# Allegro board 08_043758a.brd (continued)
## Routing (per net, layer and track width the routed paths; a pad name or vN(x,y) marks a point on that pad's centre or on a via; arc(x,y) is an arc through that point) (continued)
ADM1177_SCL: length 49.8
  TOP w0.127: U11.7 64.81,13.61 R81.2 65.9,12.52 67.54,12.52 69.31,10.74 v1(74.14,10.74) ; U10.6 v1(90.78,38.16)
  L5_SIG w0.127: v1(90.78,38.16) 89.77,37.15 89.77,28.31 83.13,21.66 79.35,21.66 78.08,20.4 78.08,14.69 v1(74.14,10.74)
ADM1177_SDA: length 50.7
  TOP w0.127: U11.6 64.37,12.96 64.62,12.71 64.62,12.28 R80.2 65.9,12.27 67.16,12.27 69.19,10.23 73.76,10.23 v1(74.14,9.85) ; v1(90.78,37.28) 90.4,37.66 U10.7
  L5_SIG w0.127: v1(74.14,9.85) 78.59,14.3 78.59,20.14 79.6,21.16 83.16,21.16 90.27,28.27 90.27,36.78 v1(90.78,37.28)
ADP2114_VIN: length 19.9
  TOP w0.203: U6.31 95.2,47.46 95.48,47.19
  TOP w0.305: U6.4 97.13,50.24 v1(97.25,50.37) ; C141.1 97.11,52.24 U6.8 ; C141.1 98.08,53.21 R56.2 98.08,54.49 v1(97.89,54.68) ; C141.1 97.14,53.79 95.51,53.79 95.2,53.49 U6.10 ; v1(97.25,46.94) 95.73,46.94 95.48,47.19
  L5_SIG w0.305: v1(97.25,46.94) 98,47.68 98,49.24 97.25,49.98 v1(97.25,50.37) 97.59,50.37 97.89,50.67 v1(97.89,54.68)
COMP_1P8V: length 2.8
  TOP w0.305: v1(97.25,49.1) 97.11,49.24 U6.2
  BOTTOM w0.508: v1(97.25,49.1) 97.38,48.97 R60.1 C142.2
COMP_1P35V: length 2.7
  TOP w0.305: C143.2 98.01,51.74 U6.7
  TOP w0.406: C143.2 98.03,51.76 C144.1
CTRL_IN0: length 53
  TOP w0.102: U4.F13 v2(56.33,28.95) ; U5.C5 v2(33.14,33.68)
  L6_SIG w0.114: v2(33.14,33.68) 33.15,33.68 33.55,34.08 33.55,34.68 33.35,34.88 31.22,34.88 30.34,34.01 30.34,32.68 30.15,32.48 28.15,32.48 27.15,31.48 27.15,25.23 30.2,22.17 53.36,22.17 56.72,25.53 56.72,26.91 56.33,27.31 v2(56.33,28.95)
CTRL_IN1: length 48
  TOP w0.102: U5.C6 v2(33.14,32.88) ; v2(56.33,26.55) 56.33,28.14 55.93,28.54 U4.F14
  L6_SIG w0.114: v2(33.14,32.88) 33.14,32.89 32.75,33.28 32.75,33.88 32.55,34.08 31.75,34.08 30.82,33.15 30.82,32.75 30.11,32.05 29.71,32.05 29.32,31.66 28.12,31.66 27.94,31.48 27.94,25.06 30.33,22.68 53.27,22.68 56.33,25.74 v2(56.33,26.55)
CTRL_IN2: length 38.6
  TOP w0.102: U5.D6 v2(32.34,32.88) ; v2(55.53,27.35) U4.G15
  L6_SIG w0.114: v2(55.53,27.35) 54.96,26.78 54.96,26.37 54.66,26.07 54.06,26.07 52.19,24.2 30.96,24.2 29.55,25.62 29.55,26.18 29.95,26.58 29.95,27.58 29.55,27.98 29.55,30.68 29.75,30.88 30.15,30.88 30.35,31.08 30.35,31.48 31.22,32.35 31.61,32.35 32.14,32.88 v2(32.34,32.88)
CTRL_IN3: length 41.6
  TOP w0.102: U4.F15 55.93,26.95 v2(55.53,26.55) ; U5.D5 v2(32.34,33.68)
  L6_SIG w0.114: v2(32.34,33.68) U5.D5 31.34,33.28 31.12,33.05 31.12,32.65 30.17,31.7 29.76,31.7 29.55,31.48 29.55,31.08 29.35,30.88 28.95,30.88 28.42,30.35 28.42,26.11 30.71,23.82 52.61,23.82 53.98,25.18 54.97,25.18 55.53,25.75 v2(55.53,26.55)
DDR3_A0: length 30.1
  TOP w0.165: U2.N3 51.22,54.27 v2(51.22,54.27) ; U4.P1 49.03,39.45 48.43,39.45 47.03,40.85 v2(43.92,40.85)
  L6_SIG w0.165: v2(43.92,40.85) 43.32,41.45 43.32,42.04 43.52,42.23 43.91,42.23 44.11,42.43 44.11,42.71 43.91,42.91 43.52,42.91 43.32,43.1 43.32,43.38 43.52,43.58 43.91,43.58 44.11,43.78 44.11,44.06 43.91,44.25 43.52,44.25 43.32,44.45 43.32,47.48 46.51,50.67 49.02,50.67 49.41,51.07 49.41,51.87 51.22,53.68 v2(51.22,54.27)
  BOTTOM w0.165: v2(51.22,54.27) 51.62,54.67 51.62,56.16 R16.1
DDR3_A1: length 33.2
  TOP w0.165: v2(43.92,41.65) 46.93,41.65 48.63,39.95 49.33,39.95 U4.N1 ; U2.P7 49.83,51.66 v2(48.03,51.66)
  L6_SIG w0.165: v2(48.03,51.66) 46,51.66 45.38,51.03 45.1,51.03 44.83,51.31 44.55,51.31 44.35,51.11 44.35,50.83 44.62,50.56 44.62,50.28 44.43,50.08 44.15,50.08 43.88,50.35 43.6,50.35 43.4,50.16 43.4,49.88 43.67,49.61 43.67,49.33 43.47,49.13 43.07,49.13 42.72,48.78 42.72,48.38 42.51,48.17 42.51,40.56 43.61,39.46 44.21,39.46 44.41,39.66 44.41,41.16 v2(43.92,41.65)
  BOTTOM w0.165: v2(48.03,51.66) 47.45,51.66 R22.1
DDR3_A2: length 35.7
  TOP w0.165: U2.P3 v2(50.42,54.27) ; U4.M1 51.13,39.75 v2(49.93,40.95)
  L5_SIG w0.165: v2(49.93,40.95) 49.53,40.95 49.23,40.65 49.23,40.35 49.93,39.65 49.93,39.35 49.53,38.95 49.53,37.95 49.13,37.55 48.93,37.55 48.73,37.75 48.73,38.75 48.53,38.95 48.23,38.95 48.03,38.75 48.03,37.65 47.87,37.49 47.59,37.49 45.83,39.25 45.83,51.2 48.5,53.87 50.02,53.87 v2(50.42,54.27)
  BOTTOM w0.165: v2(50.42,54.27) 50.02,53.87 49.3,53.87 48.61,54.56 47.45,54.56 R17.1
DDR3_A3: length 31.5
  TOP w0.165: U4.M4 v2(50.73,36.95) ; U2.N2 v2(51.22,55.07)
  L5_SIG w0.165: v2(50.73,36.95) 51.02,36.95 51.13,37.06 51.13,37.97 51.48,38.33 51.48,38.63 51.28,38.83 50.9,38.83 50.73,39 50.73,42.75 50.53,42.95 49.93,42.95 49.53,43.35 49.53,44.55 49.71,44.73 50.13,44.73 50.33,44.93 50.33,45.21 50.13,45.4 49.73,45.4 49.53,45.6 49.53,45.88 49.73,46.08 50.13,46.08 50.33,46.27 50.33,46.55 50.13,46.75 49.73,46.75 49.53,46.95 49.53,47.23 49.73,47.42 50.13,47.42 50.33,47.62 50.33,48.06 50.12,48.27 49.92,48.27 49.73,48.46 49.73,49.56 50.04,49.87 50.64,49.87 50.82,50.04 50.82,51.73 51,51.92 51.51,51.92 51.69,52.09 51.69,52.58 51.85,52.74 52.59,52.74 52.75,52.9 52.75,53.12 52.59,53.28 51.85,53.28 51.69,53.44 51.69,53.74 51.85,53.9 52.6,53.9 52.76,54.06 52.76,54.28 52.6,54.44 51.65,54.44 51.46,54.63 51.46,54.83 v2(51.22,55.07)
  BOTTOM w0.165: v2(51.22,55.07) 50.94,55.07 50.82,55.2 50.82,56.16 R23.1
DDR3_A4: length 26.7
  TOP w0.165: v2(50.42,50.27) U2.P8 ; v2(47.33,38.65) 48.23,37.75 49.13,37.75 U4.P3
  L6_SIG w0.165: v2(50.42,50.27) 50.83,49.86 50.83,48.28 50.62,48.07 49.82,48.07 46.41,44.66 46.41,41.76 46.71,41.46 48.91,41.46 49.13,41.25 49.13,40.75 48.84,40.46 48.04,40.46 47.81,40.23 47.81,39.66 47.61,39.46 46.71,39.46 46.51,39.26 46.51,38.46 46.72,38.25 46.93,38.25 v2(47.33,38.65)
  BOTTOM w0.165: R18.1 47.64,50.67 50.02,50.67 v2(50.42,50.27)
DDR3_A5: length 24
  TOP w0.165: U2.P2 v2(50.42,55.07) ; v2(49.11,36.96) U4.P4
  L5_SIG w0.165: v2(49.11,36.96) 49.5,37.35 50.13,37.35 50.33,37.55 50.33,38.05 50.33,38.05 50.45,38.17 50.45,38.73 50.33,38.85 50.33,42.35 50.13,42.55 49.73,42.55 49.13,43.15 49.13,48.16 49.33,48.36 49.33,49.78 50.43,50.88 50.43,51.98 51.23,52.78 51.23,53.56 50.82,53.97 50.82,54.67 v2(50.42,55.07)
  BOTTOM w0.165: v2(50.42,55.07) 50.14,55.07 50.02,55.2 50.02,56.16 R24.1
DDR3_A6: length 26.8
  TOP w0.165: v2(48.01,48.67) 48.81,49.47 49.62,49.47 U2.R8 ; v2(46.72,36.55) 47.13,36.15 49.13,36.15 U4.P5
  L6_SIG w0.165: v2(48.01,48.67) 47.62,49.07 47.29,49.07 47.09,48.87 47.09,48.49 47.33,48.26 47.33,47.96 47.13,47.76 46.63,47.76 46.42,47.96 46.42,48.74 46.29,48.87 46.01,48.87 45.61,48.47 45.61,48.11 45.84,47.88 45.84,47.6 45.65,47.4 45.37,47.4 45.1,47.67 44.82,47.67 44.21,47.07 44.21,45.26 45.21,44.26 45.21,39.16 44.91,38.86 44.91,38.36 v2(46.72,36.55)
  BOTTOM w0.165: R19.1 48.63,48.17 48.52,48.17 v2(48.01,48.67)
DDR3_A7: length 30.3
  TOP w0.165: U4.M5 v2(50.73,36.15) ; U2.R2 v2(49.62,55.07)
  L5_SIG w0.165: v2(49.62,55.07) 49.31,55.37 48.82,55.37 45.02,51.58 45.02,37.95 45.67,37.3 46.57,37.3 47.73,36.15 48.63,36.15 49.03,35.75 50.33,35.75 v2(50.73,36.15)
  BOTTOM w0.165: R25.1 48.12,55.87 48.63,55.36 49.33,55.36 v2(49.62,55.07)
DDR3_A8: length 24.1
  TOP w0.165: v2(48.01,49.47) 48.41,49.87 U2.T8 ; v2(46.72,35.75) 47.12,35.35 49.13,35.35 U4.P6
  L6_SIG w0.165: v2(48.01,49.47) 46.01,49.47 43.81,47.27 43.81,45.06 44.81,44.06 44.81,39.46 44.51,39.16 44.51,38.06 46.42,36.16 v2(46.72,35.75)
  BOTTOM w0.165: v2(48.01,49.47) 47.52,48.97 47.52,48.55 R20.1
DDR3_A9: length 27.7
  TOP w0.165: U4.N4 v2(49.93,36.95) ; v2(49.61,54.27) U2.R3
  L5_SIG w0.165: v2(49.61,54.27) 48.34,54.27 45.43,51.36 45.43,39.05 47.43,37.05 48.33,37.05 48.93,36.45 49.43,36.45 v2(49.93,36.95)
  BOTTOM w0.165: R26.1 47.87,54.94 48.95,54.94 v2(49.61,54.27)
DDR3_A10: length 39.2
  TOP w0.165: v2(53.13,40.35) 53.13,39.35 U4.J1 ; v2(52.81,51.07) 53.21,50.67 U2.L7
  L5_SIG w0.165: v2(53.13,40.35) 53.53,39.95 53.53,36.6 53.68,36.45 54.13,36.45 54.33,36.25 54.33,35.95 54.13,35.75 52.93,35.75 52.73,35.95 52.73,39.95 52.32,40.36 52.32,41.18 52.73,41.59 52.93,41.59 53.13,41.79 53.13,42.06 52.93,42.26 52.73,42.26 52.53,42.46 52.53,42.74 52.73,42.93 53.03,42.93 53.32,43.22 53.32,43.45 53.1,43.67 52.32,43.67 52.13,43.86 52.13,44.06 52.35,44.28 53.1,44.28 53.23,44.41 53.23,45.16 53.03,45.36 52.73,45.36 52.24,44.87 51.92,44.87 51.63,45.15 51.63,45.54 51.83,45.74 52.23,45.74 52.43,45.94 52.43,46.22 52.23,46.41 51.83,46.41 51.63,46.62 51.63,47.26 51.83,47.46 52.13,47.46 52.43,47.16 52.43,47.15 53.43,47.15 53.63,47.35 53.63,47.73 53.43,47.93 52.63,47.93 52.43,48.13 52.43,48.41 52.63,48.6 52.93,48.6 53.13,48.8 53.13,49.6 53.63,50.1 53.63,50.51 53.48,50.66 53.23,50.66 v2(52.81,51.07)
  BOTTOM w0.165: v2(52.81,51.07) 52.22,51.07 51.62,50.47 51.62,48.28 R21.1
DDR3_A11: length 32.7
  TOP w0.165: v2(48.02,50.27) 49.62,50.27 U2.R7 ; U4.L2 51.53,38.55 51.53,39.95 50,41.48 48,41.48 v2(47.43,42.05)
  L5_SIG w0.165: v2(48.02,50.27) 47.62,49.87 47.62,49.27 47.81,49.07 48.22,49.07 48.42,48.87 48.42,48.35 48.23,48.16 47.83,48.16 47.63,47.96 47.63,47.52 47.82,47.32 48.53,47.32 48.73,47.12 48.73,46.84 48.53,46.65 47.82,46.65 47.63,46.45 47.63,46.17 47.82,45.97 48.53,45.97 48.73,45.77 48.73,45.5 48.53,45.3 47.82,45.3 47.63,45.1 47.63,44.82 47.82,44.63 48.53,44.63 48.73,44.43 48.73,44.15 48.53,43.95 47.72,43.95 47.53,43.76 47.53,43.45 47.73,43.25 48.43,43.25 48.93,42.75 48.93,41.65 48.73,41.45 48.33,41.45 47.98,41.1 47.98,39.9 47.63,39.55 47.13,39.55 46.81,39.87 46.81,40.72 47.43,41.34 v2(47.43,42.05)
  BOTTOM w0.165: v2(48.02,50.27) 47.23,49.49 R27.1
DDR3_A12: length 30.5
  TOP w0.165: v2(48.43,40.95) 49.14,40.95 50.75,39.34 50.75,38.52 U4.M2 ; U2.N7 51.22,51.07 v2(51.22,51.07)
  L6_SIG w0.165: v2(51.22,51.07) 51.22,51.44 51.98,52.21 51.98,52.51 51.73,52.76 51.5,52.76 50.53,51.79 50.53,51.06 50.01,50.54 50.01,50.24 49.83,50.06 49.51,50.06 49.31,49.86 49.31,49.58 49.51,49.38 49.83,49.38 50.03,49.19 50.03,48.88 47.71,46.57 45.31,46.57 45.09,46.35 45.09,45.88 45.31,45.66 45.81,45.66 46.01,45.46 46.01,41.26 46.32,40.95 v2(48.43,40.95)
  BOTTOM w0.165: R28.1 50.82,48.28 50.82,50.67 v2(51.22,51.07)
DDR3_A13: length 30.8
  TOP w0.165: U2.T3 48.82,53.47 v2(48.82,53.47) ; U4.K2 52.33,38.55 52.33,39.89 50.23,41.98 v2(49.93,41.98)
  L5_SIG w0.165: v2(49.93,41.98) 48.83,40.88 48.83,40.15 47.83,39.15 46.72,39.15 46.23,39.65 46.23,45.35 46.63,45.75 46.63,46.15 46.23,46.55 46.23,46.83 46.42,47.03 46.63,47.03 46.83,47.23 46.83,47.5 46.63,47.7 46.42,47.7 46.23,47.9 46.23,48.18 46.42,48.37 46.63,48.37 46.83,48.57 46.83,48.85 46.63,49.05 46.42,49.05 46.23,49.24 46.23,49.52 46.42,49.72 46.63,49.72 46.83,49.92 46.83,50.2 46.63,50.39 46.35,50.39 46.23,50.52 46.23,51.06 48.03,52.86 48.2,52.86 v2(48.82,53.47)
  BOTTOM w0.165: R34.1 48.22,54.07 v2(48.82,53.47)
DDR3_A14: length 35.5
  TOP w0.165: U4.K1 52.73,40.09 50.32,42.49 48.87,42.49 v2(48.43,42.05) ; v2(48.82,51.07) U2.T7
  L5_SIG w0.165: v2(48.43,42.05) 48.43,42.63 48.3,42.75 47.43,42.75 47.07,42.39 46.79,42.39 46.63,42.55 46.63,43.65 46.82,43.85 47.03,43.85 47.23,44.04 47.23,44.32 47.03,44.52 46.82,44.52 46.63,44.72 46.63,45 46.82,45.19 47.03,45.19 47.22,45.38 47.22,50.47 46.83,50.86 46.83,51.06 47.04,51.27 47.38,51.27 47.61,51.5 47.61,51.84 47.84,52.07 48.24,52.07 49.62,53.45 50.5,53.45 50.71,53.24 50.71,52.78 50.5,52.56 50.23,52.56 50.03,52.76 49.73,52.76 49.57,52.6 49.57,52.32 50.03,51.87 50.03,51.56 49.83,51.36 49.59,51.36 49.08,51.86 48.83,51.86 48.13,51.16 48.13,50.86 48.53,50.46 48.53,50.16 48.74,49.95 48.92,49.95 49.23,50.26 49.23,50.66 v2(48.82,51.07)
  BOTTOM w0.165: v2(48.82,51.07) 48.82,51.39 48.69,51.51 48.46,51.51 48.02,51.07 R29.1
DDR3_BA0: length 34
  TOP w0.165: U2.M2 v2(52.02,55.07) ; U4.M6 v2(50.73,35.35)
  L5_SIG w0.165: v2(52.02,55.07) 52.58,55.63 52.58,57.58 52.77,57.78 53.02,57.78 53.22,57.57 53.22,53.15 53.39,52.98 53.64,52.98 53.87,52.75 53.87,52.3 53.57,51.99 52.14,51.99 51.84,51.69 51.84,50.74 51.62,50.52 51.62,50.04 50.93,49.36 50.93,48.28 50.82,48.17 50.82,44.33 50.6,44.11 50.13,44.11 49.93,43.92 49.93,43.64 50.13,43.44 50.93,43.44 51.13,43.24 51.13,39.55 51.93,38.75 51.93,35.94 51.73,35.75 51.13,35.75 v2(50.73,35.35)
  BOTTOM w0.165: R35.1 52.72,55.57 52.52,55.37 52.32,55.37 v2(52.02,55.07)
DDR3_BA1: length 30.4
  TOP w0.165: v2(47.34,39.96) 48.35,38.95 U4.R1 ; v2(51.22,50.27) U2.N8
  L6_SIG w0.165: v2(51.22,50.27) 51.22,48.07 50.8,47.65 50,47.65 48.13,45.78 48.13,44.95 47.76,44.59 47.34,44.59 47.11,44.36 47.11,44.14 47.34,43.91 47.76,43.91 48,43.68 48,43.36 47.83,43.2 47.44,43.2 47.21,42.97 47.21,42.75 47.44,42.52 49.33,42.52 49.53,42.33 49.53,40.27 49.11,39.86 48.51,39.86 48.23,39.57 48.23,38.85 47.33,37.95 47.33,37.47 47.05,37.2 46.67,37.2 46.11,37.76 46.11,40.36 46.28,40.53 47.14,40.53 47.34,40.34 v2(47.34,39.96)
  BOTTOM w0.165: R30.1 51.22,47.89 v2(51.22,50.27)
DDR3_BA2: length 28.7
  TOP w0.165: v2(53.32,52.47) 52.42,53.37 U2.M3 ; U4.N6 v2(49.93,35.35)
  L6_SIG w0.165: v2(53.32,52.47) 53.61,52.76 53.82,52.76 54.02,52.57 54.02,52.17 53.21,51.36 53.21,48.04 52.33,47.15 52.33,46.65 52.13,46.45 50.7,46.45 49.43,45.18 49.43,44.15 49.63,43.95 49.93,43.95 50.33,44.35 50.63,44.35 51.32,43.66 51.32,41.26 51.72,40.86 51.72,39.96 51.41,39.66 51.02,39.66 50.33,38.97 50.33,36.78 50.57,36.55 50.97,36.55 51.13,36.38 51.13,35.9 50.98,35.75 50.33,35.75 v2(49.93,35.35)
  BOTTOM w0.165: R36.1 52.54,51.69 v2(53.32,52.47)
DDR3_CAS#: length 28.5
  TOP w0.165: v2(53.62,53.46) 54.02,53.86 U2.K3 ; v2(48.21,35.75) U4.R5
  L6_SIG w0.165: v2(53.62,53.46) 52.82,52.66 52.82,51.74 52.22,51.14 52.22,50.87 52.73,50.36 52.73,48.28 51.32,46.87 50.52,46.87 49.01,45.36 49.01,43.67 49.22,43.46 50.52,43.46 50.83,43.15 50.83,40.17 49.53,38.87 49.53,37.8 49.36,37.64 48.81,37.64 48.65,37.47 48.65,36.43 48.93,36.15 49.3,36.15 49.43,36.02 49.43,35.45 49.16,35.18 48.78,35.18 v2(48.21,35.75)
  BOTTOM w0.165: R32.1 52.94,52.87 53.49,52.87 53.63,53.01 53.63,53.45 v2(53.62,53.46)
DDR3_CK_N: length 32.4
  TOP w0.127: v2(53.61,51.07) 54.02,50.67 U2.K7 ; U4.N2 v2(49.93,38.55)
  BOTTOM w0.127: R142.2 53.61,51.66 v2(53.61,51.07) 53.22,50.68 53.22,50.44 53.43,50.23 53.61,50.23 53.94,50.56 54.12,50.56 54.42,50.26 54.42,47.57 55.09,46.9 58.79,46.9 59.14,46.55 59.14,46.06 58.82,45.74 54.85,45.74 54.32,45.21 54.32,44.15 54.06,43.89 51.99,43.89 50.81,45.06 49.92,45.06 49.12,44.26 49.12,43.5 50.95,41.66 50.95,38.95 50.3,38.3 50.18,38.3 v2(49.93,38.55)
DDR3_CK_P: length 31.5
  TOP w0.127: U2.J7 v2(54.42,51.07) ; U4.N3 v2(49.93,37.75)
  BOTTOM w0.127: v2(49.93,37.75) 50.2,38.02 50.41,38.02 51.23,38.84 51.23,41.78 49.4,43.62 49.4,44.15 50.03,44.78 50.7,44.78 51.87,43.61 54.18,43.61 54.6,44.03 54.6,45.09 54.97,45.46 58.94,45.46 59.42,45.94 59.42,46.66 58.91,47.18 55.21,47.18 54.7,47.69 54.7,50.38 54.42,50.66 v2(54.42,51.07) 54.42,51.47 R142.1
DDR3_CKE: length 34.9
  TOP w0.165: v2(53.62,48.67) U2.K9 ; U4.L3 v2(51.53,37.75)
  L6_SIG w0.165: v2(51.53,37.75) U4.L3 53.4,37.35 53.63,37.58 53.63,37.93 53.41,38.15 52.83,38.15 52.64,38.35 51.03,38.35 50.86,38.52 50.86,38.79 51.02,38.96 53.4,38.96 53.64,39.2 53.64,39.58 53.38,39.85 52.33,39.85 52.13,40.04 52.13,40.32 52.33,40.52 52.53,40.52 52.73,40.72 52.73,41.01 52.53,41.21 52.13,41.21 51.93,41.4 51.93,41.68 52.13,41.88 53,41.88 53.13,42.01 53.13,42.42 53,42.55 52.33,42.55 52.13,42.75 52.13,43.05 52.3,43.22 53.28,43.22 53.43,43.38 53.43,43.75 53.28,43.9 51.73,43.9 51.53,44.09 51.53,44.37 51.73,44.57 52.93,44.57 53.13,44.77 53.13,45.05 52.93,45.24 51.32,45.24 51.03,44.95 50.73,44.95 50.53,45.15 50.53,45.45 50.99,45.92 53.29,45.92 53.62,46.24 v2(53.62,48.67)
  BOTTOM w0.165: R38.1 53.63,47.88 53.82,48.07 53.82,48.47 v2(53.62,48.67)
DDR3_CS#: length 29.4
  TOP w0.165: U2.L2 v2(52.82,55.07) ; U4.R2 48.47,38.15 47.37,39.25 46.32,39.25 45.63,39.95 v2(43.92,39.95)
  L6_SIG w0.165: v2(43.92,39.95) 42.92,40.95 42.92,47.68 46.31,51.07 48.11,51.07 50.82,53.78 50.82,54.48 51.01,54.67 52.23,54.67 v2(52.82,55.07)
  BOTTOM w0.165: v2(52.82,55.07) 53.09,55.07 53.22,55.2 53.22,56.15 R39.1
DDR3_DM0: length 26.5
  TOP w0.165: v2(59.22,52.67) 59.22,51.87 U2.E7 ; v2(63.13,38.95) 62.25,39.82 60.01,39.82 U4.B1
  L6_SIG w0.165: v2(63.13,38.95) 64.53,40.35 64.53,49.56 64.18,49.91 63.9,49.91 63.68,49.69 63.4,49.69 63.2,49.89 63.2,50.16 63.52,50.49 63.52,51.37 62.63,52.27 59.62,52.27 v2(59.22,52.67)
DDR3_DM1: length 23.1
  TOP w0.165: U4.D3 v2(57.93,37.75) ; v2(59.22,53.47) U2.D3
  L5_SIG w0.165: v2(59.22,53.47) 58.52,52.78 58.52,51.05 58.02,50.54 58.02,48.16 55.63,45.78 55.63,42.35 54.23,40.95 54.23,37.55 54.42,37.35 57.53,37.35 v2(57.93,37.75)
DDR3_DQ0: length 28.4
  TOP w0.165: U2.E3 58.42,54.27 v2(58.42,54.27) ; U4.D4 v2(57.93,36.95)
  L6_SIG w0.165: v2(57.93,36.95) 58.33,36.55 61.23,36.55 62.63,37.95 62.63,39.15 64.13,40.65 64.13,47.76 63.79,48.1 63.79,48.38 63.96,48.55 63.96,48.83 63.76,49.02 63.48,49.02 63.31,48.85 63.03,48.85 62.63,49.26 62.63,50.76 61.92,51.47 59.72,51.47 58.77,52.42 58.77,53.67 58.99,53.88 58.99,54.09 58.81,54.27 v2(58.42,54.27)
DDR3_DQ1: length 24.7
  TOP w0.165: v2(62.13,38.55) 61.73,38.15 U4.A2 ; v2(58.02,52.27) 57.22,51.47 U2.F7
  L6_SIG w0.165: v2(62.13,38.55) 62.13,40.07 62.72,40.66 63.32,40.66 63.63,40.97 63.63,46.94 63.47,47.11 62.24,47.11 62.07,47.27 62.07,47.6 62.24,47.77 62.77,47.77 62.93,47.93 62.93,48.26 62.77,48.43 62.29,48.43 62.12,48.6 62.12,50.47 61.92,50.67 59.62,50.67 v2(58.02,52.27)
DDR3_DQ2: length 23.2
  TOP w0.165: U2.F2 v2(56.82,55.07) ; U4.C4 v2(58.73,36.95)
  L6_SIG w0.165: v2(58.73,36.95) 58.33,37.35 56.94,37.35 56.73,37.56 56.73,39.05 55.13,40.65 55.13,41.15 54.73,41.55 54.73,43.15 54.41,43.47 54.41,49.87 54.82,50.27 54.82,53.68 55.81,54.67 56.42,54.67 v2(56.82,55.07)
DDR3_DQ3: length 28.4
  TOP w0.165: v2(58.02,51.47) 57.62,51.07 57.62,50.27 U2.F8 ; U4.C1 60.03,40.65 v2(61.63,40.65)
  L6_SIG w0.165: v2(58.02,51.47) 58.02,51.37 59.33,50.06 60.33,50.06 60.53,49.86 60.53,49 60.69,48.84 60.98,48.84 61.15,48.67 61.15,48.34 60.98,48.18 60.69,48.18 60.53,48.01 60.53,47.45 61.35,46.63 62.93,46.63 63.13,46.43 63.13,46.13 62.89,45.89 61.65,45.89 61.42,45.66 61.42,45.36 61.62,45.16 62.97,45.16 63.14,44.99 63.14,44.66 62.97,44.5 62.2,44.5 62.03,44.33 62.03,44 62.2,43.84 62.97,43.84 63.14,43.67 63.14,43.34 62.97,43.18 62.4,43.18 62.23,43.01 62.23,42.68 62.4,42.52 62.97,42.52 63.14,42.35 63.14,42.02 62.97,41.86 62.4,41.86 62.23,41.69 62.23,41.25 v2(61.63,40.65)
DDR3_DQ4: length 21.8
  TOP w0.165: v2(56.83,52.66) 55.62,53.87 U2.H3 ; v2(59.53,36.95) U4.B4
  L6_SIG w0.165: v2(56.83,52.66) 57.43,52.66 57.62,52.47 57.62,51.17 58.02,50.77 58.02,47.57 59.52,46.06 59.52,45.67 59.82,45.37 60.22,45.37 60.53,45.05 60.53,40.15 61.34,39.34 61.34,37.76 60.93,37.35 59.93,37.35 v2(59.53,36.95)
DDR3_DQ5: length 22.8
  TOP w0.165: v2(60.33,36.95) U4.A4 ; v2(58.42,47.87) 57.02,47.87 56.02,48.87 56.02,49.47 U2.H8
  L6_SIG w0.165: v2(60.33,36.95) 61.03,36.95 61.73,37.65 61.73,39.65 61.03,40.35 61.03,40.99 61.19,41.16 61.52,41.16 61.69,41.32 61.69,41.65 61.52,41.82 61.19,41.82 61.03,41.98 61.03,43.93 61.19,44.1 61.52,44.1 61.69,44.26 61.69,44.59 61.52,44.76 61.19,44.76 61.03,44.92 61.03,45.26 60.69,45.6 60.69,45.83 60.92,46.07 60.92,46.3 60.69,46.54 60.45,46.54 60.22,46.3 59.99,46.3 59.02,47.27 59.02,47.47 59.47,47.91 59.47,48.52 59.32,48.67 58.96,48.67 58.82,48.52 58.82,48.27 v2(58.42,47.87)
DDR3_DQ6: length 23.9
  TOP w0.165: U2.G2 v2(56.02,54.27) ; U4.C3 v2(58.73,37.75)
  L6_SIG w0.165: v2(58.73,37.75) 58.33,38.15 57.63,38.15 57.53,38.26 57.53,39.51 57.52,39.52 57.52,39.86 57.12,40.26 56.22,40.26 55.63,40.85 55.63,43.43 55.31,43.76 54.94,43.76 54.81,43.89 54.81,44.29 55.01,44.49 55.62,44.49 55.81,44.69 55.81,44.97 55.62,45.16 55.01,45.16 54.81,45.36 54.81,45.64 55.01,45.84 55.22,45.84 55.41,46.03 55.41,46.31 55.22,46.51 55.01,46.51 54.81,46.71 54.81,46.99 55.01,47.18 55.22,47.18 55.41,47.38 55.41,47.77 55.22,47.97 55.02,47.97 54.81,48.17 54.81,49.67 55.23,50.09 55.23,53.49 v2(56.02,54.27)
DDR3_DQ7: length 21.8
  TOP w0.165: U4.A3 v2(60.34,37.75) ; U2.H7 55.62,50.67 v2(56.82,51.87)
  L6_SIG w0.165: v2(56.82,51.87) 57.22,51.47 57.22,50.88 57.52,50.57 57.52,49.37 57.22,49.07 57.22,48.21 57.09,48.09 56.94,48.09 56.72,47.87 56.72,47.57 56.88,47.41 57.47,47.41 57.73,47.15 57.73,46.06 57.93,45.85 58.11,45.85 58.43,46.17 58.71,46.17 58.91,45.97 58.91,45.69 58.59,45.38 58.59,45.1 59.53,44.16 59.53,42.88 59.73,42.69 59.83,42.69 60.03,42.49 60.03,42.21 59.83,42.01 59.73,42.01 59.53,41.82 59.53,41.54 59.73,41.34 59.83,41.34 60.03,41.14 60.03,40.86 59.83,40.67 59.73,40.67 59.53,40.47 59.53,39.45 60.83,38.15 60.83,37.85 60.73,37.75 v2(60.34,37.75)
DDR3_DQ8: length 28.2
  TOP w0.165: U4.E1 56.73,38.95 57.13,39.35 v2(57.13,39.35) ; v2(60.02,52.67) 59.62,52.27 59.62,51.47 U2.D7
  L5_SIG w0.165: v2(60.02,52.67) 60.42,52.27 60.42,51.67 60.62,51.47 60.99,51.47 61.23,51.71 61.23,52.38 61.5,52.66 62.63,52.66 63.35,51.94 63.35,51.56 62.92,51.13 62.92,50.87 63.11,50.68 63.44,50.68 63.62,50.87 64.02,50.87 64.22,50.67 64.22,41.86 62.12,39.76 57.54,39.76 v2(57.13,39.35)
DDR3_DQ9: length 25.8
  TOP w0.165: v2(57.13,38.55) U4.D1 ; v2(60.02,53.47) U2.C3
  L5_SIG w0.165: v2(57.13,38.55) 57.63,39.05 59.83,39.05 60.03,38.85 60.63,38.85 61.14,39.36 62.32,39.36 64.92,41.96 64.92,49.59 64.62,49.89 64.62,50.25 64.72,50.35 64.72,51.17 62.52,53.37 62.22,53.37 61.91,53.06 60.43,53.06 v2(60.02,53.47)
DDR3_DQ10: length 28.6
  TOP w0.165: U2.C8 60.01,50.26 v2(61.62,50.26) ; U4.E2 56.33,38.55 56.33,39.35 57.03,40.05 v2(57.03,41.05)
  L5_SIG w0.165: v2(61.62,50.26) 62.12,49.77 62.12,48.67 62.34,48.45 63.24,48.45 63.42,48.27 63.42,47.04 63.22,46.85 62.82,46.85 62.62,46.65 62.62,46.37 62.82,46.17 63.22,46.17 63.42,45.98 63.42,45.7 63.22,45.5 63.02,45.5 62.82,45.3 62.82,45.02 63.34,44.51 63.34,44.18 62.46,43.3 62.46,42.92 63.14,42.25 63.14,41.98 62.54,41.39 62.25,41.39 62.02,41.62 62.02,42.52 61.88,42.66 61.32,42.66 61.12,42.46 61.12,41.86 61.52,41.46 61.52,41.24 61.03,40.75 60.44,40.75 60.22,40.96 59.82,40.96 59.61,40.75 58.76,40.75 58.63,40.88 58.63,41.55 58.13,42.05 57.73,42.05 57.33,41.65 57.33,41.35 v2(57.03,41.05)
DDR3_DQ11: length 27
  TOP w0.165: v2(60.02,54.27) U2.C2 ; v2(57.13,37.75) U4.E3
  L5_SIG w0.165: v2(60.02,54.27) 62.32,54.27 65.32,51.27 65.32,41.76 62.51,38.95 61.41,38.95 60.61,38.15 57.53,38.15 v2(57.13,37.75)
DDR3_DQ12: length 29.5
  TOP w0.165: v2(61.62,51.07) U2.A7 ; v2(56.33,37.75) U4.F3
  L5_SIG w0.165: v2(56.33,37.75) 56.33,39.36 57.53,40.56 57.53,41.05 57.73,41.25 57.97,41.25 58.13,41.09 58.13,40.42 58.39,40.16 61.92,40.16 63.82,42.07 63.82,42.56 63.6,42.78 63.32,42.78 63.12,42.98 63.12,43.26 63.32,43.46 63.61,43.46 63.82,43.66 63.82,48.77 63.65,48.94 62.82,48.94 62.62,49.14 62.62,49.42 62.82,49.61 63.6,49.61 63.82,49.84 63.82,50.07 63.59,50.3 62.39,50.3 62.19,50.5 62.19,50.94 62.72,51.47 62.72,51.78 62.23,52.26 61.83,52.26 61.62,52.05 v2(61.62,51.07)
DDR3_DQ13: length 28.8
  TOP w0.165: v2(55.13,42.45) 55.13,39.85 55.03,39.55 55.03,39.25 U4.G1 ; v2(61.62,55.07) U2.A2
  L5_SIG w0.165: v2(61.62,55.07) 61.22,55.47 55.02,55.47 54.62,55.07 54.62,54.74 55.03,54.32 55.03,50.69 54.82,50.47 54.42,50.47 54.13,50.18 54.13,47.96 54.34,47.75 55.33,47.75 55.61,47.47 55.61,47.16 55.32,46.86 54.11,46.86 53.93,46.68 53.93,45.85 54.22,45.56 54.22,42.47 54.59,42.09 54.77,42.09 v2(55.13,42.45)
DDR3_DQ14: length 28.5
  TOP w0.165: U4.H1 54.33,40.25 v2(54.73,40.65) ; U2.B8 60.82,49.47 60.82,48.67 v2(60.02,47.87)
  L5_SIG w0.165: v2(60.02,47.87) 59.72,47.58 59.54,47.58 59.42,47.7 59.42,50.17 59.26,50.33 58.98,50.33 58.82,50.17 58.82,46.37 58.62,46.17 58.42,46.17 58.22,46.37 58.22,47.17 58.02,47.37 57.72,47.37 57.53,47.17 57.53,46.37 57.33,46.17 56.77,46.17 56.54,45.93 56.54,45.7 56.77,45.47 58.47,45.47 58.72,45.22 58.72,44.94 58.52,44.75 56.26,44.75 56.03,44.52 56.03,44.2 56.26,43.97 57.11,43.97 57.32,43.77 57.32,43.54 57.15,43.37 56.82,43.37 56.62,43.17 56.62,42.84 54.73,40.95 v2(54.73,40.65)
DDR3_DQ15: length 31.7
  TOP w0.165: v2(55.13,43.15) 54.73,42.75 54.73,41.55 53.93,40.75 53.93,38.55 U4.H2 ; v2(61.62,53.47) U2.A3
  L5_SIG w0.165: v2(61.62,53.47) U2.A3 59.71,53.87 58.91,54.67 55.64,54.67 55.43,54.46 55.43,52.46 56.42,51.47 57.12,51.47 57.32,51.27 57.32,49.27 57.12,49.07 56.41,49.07 55.53,49.96 55,49.96 54.63,49.58 54.63,48.48 54.84,48.27 55.82,48.27 56.42,47.67 56.42,47.27 55.42,46.27 54.82,46.27 54.63,46.08 54.63,43.65 v2(55.13,43.15)
DDR3_DQS0_N: length 24.1
  TOP w0.127: U2.G3 56.82,53.47 v2(56.82,53.47) ; U4.B2 v2(59.53,38.55)
  L6_SIG w0.14: v2(59.53,38.55) 59.05,39.03 59.05,41.49 58.67,41.87 57.02,41.87 56.83,42.06 56.83,42.33 57.02,42.51 58.67,42.51 59.05,42.89 59.05,43.84 58.36,44.52 57.92,44.52 57.19,43.78 56.95,43.78 56.58,44.15 56.58,44.33 57.3,45.05 57.3,45.58 56.22,46.66 56.22,53.22 56.47,53.47 v2(56.82,53.47)
DDR3_DQS0_P: length 24.6
  TOP w0.127: U4.C2 v2(58.73,38.55) ; U2.F3 v2(56.82,54.27)
  L6_SIG w0.14: v2(58.73,38.55) 58.73,41.36 58.54,41.55 56.89,41.55 56.52,41.93 56.52,42.46 56.89,42.83 58.54,42.83 58.73,43.02 58.73,43.7 58.23,44.2 58.05,44.2 57.32,43.47 56.82,43.47 56.26,44.02 56.26,44.46 56.98,45.18 56.98,45.45 55.9,46.53 55.9,53.35 v2(56.82,54.27)
DDR3_DQS1_N: length 28.1
  TOP w0.127: U4.F2 v2(55.53,38.55) ; v2(60.82,51.07) U2.B7
  L5_SIG w0.14: v2(60.82,51.07) 60.34,50.59 60.34,50.3 60.94,49.7 60.94,48.4 61.16,48.17 61.86,48.17 62.32,47.71 62.32,47.07 61.91,46.66 60.46,46.66 60.24,46.43 60.24,46.11 60.46,45.89 61.71,45.89 62.2,45.39 62.2,43.95 61.8,43.55 60.83,43.55 59.91,44.48 59.5,44.48 59.13,44.1 59.13,43.83 60.3,42.65 60.3,42.07 59.89,41.65 59.3,41.65 58.13,42.83 57.76,42.83 55.63,40.71 55.63,40.23 55.05,39.64 55.05,38.87 55.16,38.76 55.32,38.76 v2(55.53,38.55)
DDR3_DQS1_P: length 27.7
  TOP w0.127: U2.C7 v2(60.02,51.07) ; U4.G2 v2(54.73,38.55)
  L5_SIG w0.14: v2(60.02,51.07) 60.02,50.17 60.62,49.57 60.62,48.27 61.03,47.85 61.72,47.85 62.01,47.57 62.01,47.2 61.78,46.98 60.33,46.98 59.92,46.56 59.92,45.98 60.33,45.57 61.58,45.57 61.89,45.26 61.89,44.08 61.67,43.87 60.96,43.87 60.04,44.79 59.37,44.79 58.81,44.23 58.81,43.7 59.98,42.52 59.98,42.2 59.76,41.97 59.44,41.97 58.26,43.15 57.63,43.15 55.31,40.84 55.31,40.36 54.73,39.77 v2(54.73,38.55)
DDR3_ODT: length 36.8
  TOP w0.165: U2.K1 v2(53.62,55.87) ; U4.K3 v2(52.33,37.75)
  L5_SIG w0.165: v2(53.62,55.87) 53.61,55.87 53.61,57.07 53.9,57.36 58.04,57.36 58.34,57.06 58.34,56.76 58.09,56.51 54.98,56.51 54.02,55.55 54.02,53.16 54.33,52.85 54.33,51.94 53.97,51.58 52.4,51.58 52.2,51.38 52.2,50.79 52.73,50.26 52.73,49.46 52.34,49.07 51.55,49.07 51.32,48.84 51.32,48.47 51.63,48.16 51.63,47.86 51.23,47.46 51.23,44.15 52.13,43.25 52.13,41.86 51.93,41.66 51.73,41.66 51.53,41.46 51.53,40.15 51.73,39.95 52.13,39.95 52.33,39.75 v2(52.33,37.75)
  BOTTOM w0.165: v2(53.62,55.87) 54.01,55.47 54.19,55.47 54.32,55.6 R33.1
DDR3_RAS#: length 28.5
  TOP w0.165: v2(48.22,34.95) 48.73,34.95 U4.R6 ; U2.J3 v2(54.42,53.47)
  L6_SIG w0.165: v2(54.42,53.47) 54.02,53.87 53.32,53.87 52.42,52.97 52.42,51.94 51.62,51.15 51.62,47.87 51.02,47.27 50.22,47.27 48.53,45.58 48.53,43.25 48.82,42.96 49.62,42.96 50.33,42.25 50.33,40.38 47.72,37.76 47.72,35.45 v2(48.22,34.95)
  BOTTOM w0.165: R37.1 53.13,53.86 54.03,53.86 v2(54.42,53.47)
DDR3_RST#: length 29
  TOP w0.165: U4.L4 v2(51.53,36.95) ; v2(47.62,55.87) 48.02,55.87 U2.T2
  L5_SIG w0.165: v2(44.32,52.02) 44.32,52.57 47.62,55.87 v2(47.62,55.87)
  BOTTOM w0.165: v2(51.53,36.95) 51.13,36.55 48.85,36.55 44.61,40.79 44.61,42.46 44.32,42.76 v2(44.32,52.02) ; v2(47.62,55.87) 47.62,56.18 R42.1
DDR3_WE#: length 28.9
  TOP w0.165: v2(45.61,38.26) 45.91,37.96 46.31,37.96 46.93,37.35 U4.R3 ; U2.L3 v2(53.62,54.27)
  L6_SIG w0.165: v2(53.62,54.27) 53.33,54.56 53.03,54.56 51.93,53.46 51.6,53.46 49.91,51.77 49.91,51.07 48.41,49.57 48.41,47.87 47.51,46.97 47.01,46.97 46.71,47.27 46.31,47.27 46.01,46.97 44.91,46.97 44.71,46.77 44.71,45.37 44.91,45.17 45.4,45.17 45.61,44.96 v2(45.61,38.26)
  BOTTOM w0.165: R31.1 52.54,54.54 52.66,54.67 53.22,54.67 v2(53.62,54.27)
FB0: length 5.3
  TOP w0.305: U3.4 v1(88.11,22.55)
  BOTTOM w0.305: R4.1 85.82,22.04 87.11,23.33 R2.2 v1(88.11,22.55)
FB_1P8V: length 15.5
  TOP w0.203: v1(96.62,47.7) 96.28,48.04 U6.32
  BOTTOM w0.305: R64.1 86.07,44.14 92.56,44.14 93.39,44.97 94.89,44.97 95.29,45.37 95.29,46.37 95.86,46.94 R65.2 95.97,47.7 v1(96.62,47.7)
FB_1P35V: length 5.3
  TOP w0.305: U6.9 96.53,52.94 v1(96.75,53.16)
  BOTTOM w0.305: R63.1 96.75,52.46 v1(96.75,53.16) 94.42,55.48 R62.2
IO_02_34_AD9361_CLKOUT: length 27.2
  TOP w0.102: v2(47.43,33.35) 47.83,33.75 49.13,33.75 U4.P8 ; U5.J6 v2(27.55,32.88)
  L6_SIG w0.114: v2(47.43,33.35) 46.92,33.85 45.73,33.85 43.1,36.48 28.94,36.48 28.74,36.28 28.74,34.27 28.55,34.08 28.15,34.08 27.95,33.88 27.95,33.28 v2(27.55,32.88)
IO_02_34_AD9361_RST: length 31.6
  TOP w0.102: v2(47.43,32.55) 47.82,32.95 49.13,32.95 U4.P9 ; U5.K5 v2(26.74,33.68)
  L5_SIG w0.114: v2(47.43,32.55) 47.83,32.95 47.83,33.63 47.34,34.11 46.33,34.11 40.87,39.57 31.21,39.57 29.57,37.93 28.68,37.93 27.14,36.39 27.14,34.08 v2(26.74,33.68)
IO_L01_34_FB_CLK: length 27.3
  TOP w0.102: U5.F10 v2(30.74,28.88) ; v2(47.53,30.95) 47.93,31.34 49.13,31.34 U4.P10
  L6_SIG w0.114: v2(47.53,30.95) 48.26,30.22 48.26,28.78 47.96,28.48 47.96,27.23 47.4,26.67 47.15,26.67 46.07,25.6 32.36,25.6 31.15,26.81 31.15,28.48 v2(30.74,28.88)
IO_L01_34_RX_D0: length 50
  TOP w0.102: v2(26.74,28.08) U5.K11 ; v2(54.73,28.15) U4.H14
  L5_SIG w0.114: v2(26.74,28.08) 26.34,27.68 26.34,26.82 26.2,26.68 26.03,26.68 25.88,26.54 25.88,26.33 26.03,26.19 26.57,26.19 26.77,25.98 26.77,25.71 26.62,25.57 26.15,25.57 26.01,25.42 26.01,25.22 26.15,25.07 26.62,25.07 26.77,24.93 26.77,24.46 29.69,21.54 29.96,21.54 30.11,21.68 30.11,22.03 30.25,22.17 30.46,22.17 30.6,22.03 30.6,21.68 30.75,21.54 30.95,21.54 31.1,21.68 31.1,22.03 31.24,22.17 31.45,22.17 31.59,22.03 31.59,21.68 31.74,21.54 31.94,21.54 32.09,21.68 32.09,22.03 32.23,22.17 32.44,22.17 32.59,22.03 32.59,21.68 32.73,21.54 32.94,21.54 33.08,21.68 33.08,22.03 33.23,22.17 33.43,22.17 33.58,22.03 33.58,21.68 33.72,21.54 33.93,21.54 34.07,21.68 34.07,22.03 34.22,22.17 34.42,22.17 34.57,22.03 34.57,21.68 34.71,21.54 34.92,21.54 35.06,21.68 35.06,22.03 35.21,22.17 35.41,22.17 35.56,22.03 35.56,21.68 35.7,21.54 36.16,21.54 36.3,21.39 36.3,20.67 36.45,20.52 36.65,20.52 36.8,20.67 36.8,21.39 36.94,21.54 37.18,21.54 37.56,21.16 39.2,21.16 39.96,20.39 51.53,20.39 54.83,23.69 54.83,27.65 54.73,27.75 v2(54.73,28.15)
IO_L01_34_RX_D1: length 49.9
  TOP w0.102: v2(53.93,28.94) U4.J13 ; U5.J12 27.55,27.28 v2(27.54,27.28)
  L5_SIG w0.114: v2(27.54,27.28) 27.54,25 28.97,23.57 30.06,23.57 30.2,23.71 30.2,24.06 30.35,24.2 30.55,24.2 30.7,24.06 30.7,23.71 30.84,23.57 31.05,23.57 31.2,23.71 31.2,24.06 31.34,24.2 31.55,24.2 31.69,24.06 31.69,23.71 31.84,23.57 32.04,23.57 32.19,23.71 32.19,24.06 32.33,24.2 32.54,24.2 32.68,24.06 32.68,23.71 32.83,23.57 33.03,23.57 33.18,23.71 33.18,24.06 33.32,24.2 33.53,24.2 33.67,24.06 33.67,23.71 33.82,23.57 34.02,23.57 34.17,23.71 34.17,24.06 34.31,24.2 34.52,24.2 34.66,24.06 34.66,23.71 34.81,23.57 35.01,23.57 35.16,23.71 35.16,24.06 35.3,24.2 35.51,24.2 35.65,24.06 35.65,23.71 35.8,23.57 36,23.57 36.15,23.71 36.15,24.06 36.29,24.2 36.5,24.2 36.64,24.06 36.64,23.71 36.79,23.57 37.03,23.57 37.17,23.71 37.17,24.06 37.32,24.2 37.52,24.2 37.67,24.06 37.67,23.34 37.82,23.19 38.06,23.19 38.73,23.85 38.93,23.85 39.08,23.71 39.08,23.5 38.62,23.05 38.62,22.84 38.76,22.7 38.97,22.7 39.43,23.15 39.63,23.15 39.78,23.01 39.78,22.8 39.32,22.35 39.32,22.14 39.46,22 39.67,22 40.13,22.45 40.33,22.45 40.48,22.31 40.48,22.1 40.02,21.65 40.02,21.44 40.3,21.16 51.03,21.16 53.53,23.66 53.53,27.75 53.93,28.15 v2(53.93,28.94)
IO_L02_34_RX_D2: length 50.2
  TOP w0.102: v2(55.53,28.15) U4.G14 ; U5.K10 v2(26.74,28.88)
  L5_SIG w0.114: v2(55.53,28.15) 55.93,27.75 55.93,26.14 55.47,25.67 55.47,23.06 52.04,19.63 33.88,19.63 33.5,20.01 33.5,20.65 33.37,20.77 33.01,20.77 32.87,20.63 32.87,20.03 32.72,19.89 32.52,19.89 32.37,20.03 32.37,20.63 32.23,20.77 32.02,20.77 31.88,20.63 31.88,20.03 31.73,19.89 31.53,19.89 31.38,20.03 31.38,20.63 31.24,20.77 29.18,20.77 24.86,25.09 24.86,25.73 25.12,25.98 25.12,26.36 24.86,26.62 24.86,27.02 25.12,27.27 25.12,27.51 24.86,27.77 24.86,28.01 25.54,28.69 25.54,29.07 25.74,29.27 26.35,29.27 v2(26.74,28.88)
IO_L02_34_RX_D3: length 49.9
  TOP w0.102: v2(27.54,28.07) U5.J11 ; U4.H13 v2(54.73,28.95)
  L5_SIG w0.114: v2(54.73,28.95) 54.23,28.45 54.23,27.95 53.93,27.65 53.93,23.42 51.28,20.77 40.22,20.77 39.07,21.92 38.91,21.92 38.59,21.6 38.39,21.6 38.24,21.75 38.24,21.95 38.58,22.29 38.58,22.43 38.45,22.55 37.57,22.55 37.43,22.41 37.43,22.06 37.28,21.92 37.08,21.92 36.93,22.06 36.93,23.04 36.79,23.19 36.58,23.19 36.44,23.04 36.44,22.06 36.29,21.92 36.09,21.92 35.94,22.06 35.94,22.41 35.8,22.55 35.29,22.55 35.14,22.7 35.14,23.04 35,23.19 34.79,23.19 34.65,23.04 34.65,22.7 34.5,22.55 34.3,22.55 34.15,22.7 34.15,23.04 34.01,23.19 33.8,23.19 33.66,23.04 33.66,22.7 33.51,22.55 33.31,22.55 33.16,22.7 33.16,23.04 33.02,23.19 32.81,23.19 32.67,23.04 32.67,22.7 32.52,22.55 32.32,22.55 32.17,22.7 32.17,23.04 32.03,23.19 31.82,23.19 31.68,23.04 31.68,22.7 31.53,22.55 31.33,22.55 31.18,22.7 31.18,23.04 31.04,23.19 30.83,23.19 30.69,23.04 30.69,22.7 30.54,22.55 30.34,22.55 30.19,22.7 30.19,23.04 30.05,23.19 29.84,23.19 29.7,23.04 29.7,22.7 29.55,22.55 29.31,22.55 27.14,24.72 27.14,27.68 v2(27.54,28.07)
IO_L03_34_RX_D4: length 51.6
  TOP w0.102: U5.K9 v2(26.74,29.68) ; U4.G12 v2(55.53,29.75)
  L5_SIG w0.114: v2(26.74,29.68) 26.35,30.07 24.93,30.07 24.48,29.63 24.48,24.84 30.07,19.25 52.3,19.25 55.87,22.82 55.87,25.47 56.73,26.34 56.73,27.35 55.93,28.15 55.93,29.14 55.73,29.35 55.6,29.35 55.53,29.42 v2(55.53,29.75)
IO_L03_34_RX_D5: length 50.6
  TOP w0.102: U4.H12 v2(54.73,29.75) ; U5.J10 v2(27.55,28.88)
  L5_SIG w0.114: v2(54.73,29.75) 55.13,29.35 55.13,23.35 51.79,20.01 39.74,20.01 38.98,20.77 37.56,20.77 36.93,20.14 36.04,20.14 35.91,20.27 35.91,21.03 35.79,21.16 35.52,21.16 35.37,21.01 35.37,20.28 35.23,20.14 35.02,20.14 34.88,20.28 34.88,21.01 34.73,21.16 34.53,21.16 34.38,21.01 34.38,20.28 34.24,20.14 34.03,20.14 33.89,20.28 33.89,21.01 33.74,21.16 29.44,21.16 25.53,25.07 25.53,28.26 25.74,28.47 27.14,28.47 27.54,28.88 v2(27.55,28.88)
IO_L04_34_RX_D6: length 55.4
  TOP w0.102: U5.K8 v2(26.74,30.48) ; U4.G11 v2(55.53,30.55)
  L5_SIG w0.114: v2(55.53,30.55) 55.93,30.15 55.93,29.55 56.13,29.35 56.53,29.35 56.73,29.15 56.73,27.95 57.03,27.65 57.27,27.65 57.53,27.39 57.53,26.63 56.37,25.47 56.37,22.69 52.55,18.87 29.82,18.87 24.1,24.58 24.1,29.79 25.19,30.88 26.35,30.88 v2(26.74,30.48)
IO_L04_34_RX_D7: length 49.6
  TOP w0.102: v2(53.13,28.15) U4.J14 ; U5.J9 v2(27.54,30.48)
  L5_SIG w0.114: v2(53.13,28.15) 52.73,27.75 52.73,24.13 50.52,21.92 43.41,21.92 43.07,22.26 42.86,22.26 42.56,21.95 42.36,21.95 42.21,22.1 42.21,22.3 42.51,22.61 42.51,22.81 42.37,22.96 42.16,22.96 41.73,22.53 41.53,22.53 41.38,22.67 41.38,22.88 41.81,23.31 41.81,23.51 39.72,25.6 38.77,25.6 38.63,25.46 38.63,25.11 38.48,24.97 38.28,24.97 38.13,25.11 38.13,25.46 37.99,25.6 36.2,25.6 36.06,25.75 36.06,26.22 35.91,26.36 35.71,26.36 35.56,26.22 35.56,25.75 35.42,25.6 35.21,25.6 35.07,25.75 35.07,26.22 34.92,26.36 34.72,26.36 34.57,26.22 34.57,25.75 34.43,25.6 34.22,25.6 34.08,25.75 34.08,26.22 33.93,26.36 33.73,26.36 33.58,26.22 33.58,25.75 33.44,25.6 33.23,25.6 33.09,25.75 33.09,26.22 32.94,26.36 32.74,26.36 32.59,26.22 32.59,25.75 32.45,25.6 32.24,25.6 32.1,25.75 32.1,26.22 31.95,26.36 31.75,26.36 31.6,26.22 31.6,25.63 31.06,25.09 29.63,25.09 29.49,25.24 29.49,26.22 29.34,26.36 29.14,26.36 28.99,26.22 28.99,25.24 28.85,25.09 28.55,25.09 28.21,25.44 28.21,29.31 27.54,29.97 v2(27.54,30.48)
IO_L05_34_RX_D8: length 49.1
  TOP w0.102: U5.K7 v2(26.74,31.28) ; v2(53.13,27.35) U4.J15
  L5_SIG w0.114: v2(26.74,31.28) 27.14,30.88 27.14,29.94 27.96,29.12 27.96,25.17 28.42,24.71 30.07,24.71 30.2,24.58 32.15,24.58 32.32,24.75 32.32,25.04 32.42,25.14 32.72,25.14 32.82,25.04 32.82,24.71 32.94,24.58 33.15,24.58 33.29,24.73 33.29,25.07 33.44,25.22 33.64,25.22 33.79,25.07 33.79,24.73 33.93,24.58 34.14,24.58 34.28,24.73 34.28,25.07 34.43,25.22 34.63,25.22 34.78,25.07 34.78,24.73 34.92,24.58 35.13,24.58 35.27,24.73 35.27,25.07 35.42,25.22 35.62,25.22 35.77,25.07 35.77,24.73 35.91,24.58 36.12,24.58 36.26,24.73 36.26,25.07 36.41,25.22 36.61,25.22 36.76,25.07 36.76,24.73 36.9,24.58 37.11,24.58 37.25,24.73 37.25,25.07 37.4,25.22 37.6,25.22 37.75,25.07 37.75,24.73 37.89,24.58 39.04,24.58 39.41,24.95 39.61,24.95 39.76,24.81 39.76,24.6 39.39,24.23 39.39,24.03 39.54,23.88 39.74,23.88 40.11,24.25 40.31,24.25 40.46,24.11 40.46,23.9 40.09,23.53 40.09,23.33 40.24,23.18 40.44,23.18 40.81,23.55 41.01,23.55 41.16,23.4 41.16,23.2 40.79,22.83 40.79,22.63 41.07,22.35 41.07,22.15 40.83,21.91 40.83,21.7 40.97,21.56 41.18,21.56 41.42,21.8 41.62,21.8 41.88,21.54 50.77,21.54 53.13,23.89 v2(53.13,27.35)
IO_L05_34_RX_D9: length 49
  TOP w0.102: v2(52.33,27.35) U4.K15 ; U5.J8 v2(27.54,31.28)
  L5_SIG w0.114: v2(52.33,27.35) 52.33,24.36 50.26,22.3 43.66,22.3 39.98,25.98 39.64,25.98 39.47,26.16 39.47,27.49 39.31,27.64 39.07,27.64 38.92,27.5 38.92,26.13 38.78,25.98 38.57,25.98 38.43,26.13 38.43,27.5 38.28,27.64 38.08,27.64 37.93,27.5 37.93,26.13 37.79,25.98 37.58,25.98 37.44,26.13 37.44,26.5 37.29,26.64 37.09,26.64 36.94,26.5 36.94,26.13 36.8,25.98 36.59,25.98 36.45,26.13 36.45,26.6 36.3,26.74 35.89,26.74 35.75,26.89 35.75,28.7 35.6,28.85 35.4,28.85 35.25,28.7 35.25,26.89 35.11,26.74 31.23,26.74 31.09,26.6 31.09,25.62 30.94,25.47 30.74,25.47 30.59,25.62 30.59,26.73 30.33,27 29.94,27 29.69,26.74 28.67,26.74 28.45,26.97 28.45,29.57 28.41,29.6 28.41,29.61 27.95,30.08 27.95,30.88 v2(27.54,31.28)
IO_L06_34_RX_D10: length 49.2
  TOP w0.102: U5.J7 v2(28.35,31.28) ; U4.H11 v2(54.73,30.55)
  L5_SIG w0.114: v2(54.73,30.55) 53.81,29.63 53.81,29.44 53.53,29.16 53.53,28.75 53.33,28.55 52.03,28.55 51.53,28.05 51.53,24.33 49.88,22.68 43.84,22.68 39.85,26.66 39.85,27.63 39.09,28.39 39.09,29.16 38.97,29.28 38.76,29.28 38.61,29.13 38.61,28.16 38.46,28.01 38.26,28.01 38.11,28.16 38.11,29.13 37.97,29.28 37.76,29.28 37.62,29.13 37.62,28.16 37.47,28.01 37.27,28.01 37.12,28.16 37.12,29.13 36.98,29.28 36.77,29.28 36.63,29.13 36.63,27.27 36.48,27.12 36.28,27.12 36.13,27.27 36.13,29.13 35.99,29.28 35.15,29.28 34.35,28.48 34.35,27.88 34.14,27.68 29.66,27.68 28.75,28.59 28.75,29.62 28.35,30.02 v2(28.35,31.28)
IO_L06_34_RX_D11: length 52.4
  TOP w0.102: U5.H8 v2(29.15,31.28) ; U4.J11 v2(53.13,30.55)
  L5_SIG w0.114: v2(29.15,31.28) 29.55,30.88 29.55,28.67 29.74,28.48 30.95,28.48 31.15,28.68 31.15,29.88 31.35,30.08 31.74,30.08 31.94,29.88 31.94,28.68 32.14,28.48 32.54,28.48 32.74,28.68 32.74,29.88 32.94,30.08 33.35,30.08 33.54,29.88 33.54,29.48 33.74,29.28 34.15,29.28 34.35,29.48 34.35,29.88 34.55,30.08 35.95,30.08 36.35,30.48 36.86,30.48 37,30.33 37,29.81 37.15,29.66 37.35,29.66 37.5,29.81 37.5,30.33 37.64,30.48 37.9,30.48 38.07,30.3 38.07,29.79 38.2,29.66 39.22,29.66 39.45,29.43 39.45,28.58 40.23,27.79 40.23,26.87 40.4,26.7 40.61,26.7 40.91,27 41.12,27 41.26,26.86 41.26,26.65 40.96,26.35 40.96,26.14 41.1,26 41.31,26 41.61,26.3 41.82,26.3 41.96,26.16 41.96,25.95 41.66,25.65 41.66,25.44 41.8,25.3 42.01,25.3 42.31,25.6 42.52,25.6 42.66,25.46 42.66,25.25 42.36,24.95 42.36,24.74 42.5,24.6 42.71,24.6 43.01,24.9 43.22,24.9 43.36,24.76 43.36,24.55 43.06,24.25 43.06,24.04 43.53,23.57 44.57,23.57 44.71,23.71 44.71,24.06 44.86,24.2 45.06,24.2 45.21,24.06 45.21,23.71 45.35,23.57 45.82,23.57 45.96,23.42 45.96,23.21 46.11,23.06 46.31,23.06 46.46,23.21 46.46,23.42 46.6,23.57 47.32,23.57 47.47,23.42 47.47,23.21 47.61,23.06 47.82,23.06 47.97,23.21 47.97,23.42 48.11,23.57 48.32,23.57 48.46,23.42 48.46,23.21 48.61,23.06 48.81,23.06 48.96,23.21 48.96,23.42 49.1,23.57 50.14,23.57 51.15,24.58 51.15,28.17 51.83,28.85 51.83,29.15 52.03,29.35 53.38,29.35 53.57,29.54 53.57,30.43 53.45,30.55 v2(53.13,30.55)
IO_L07_34_RX_FRAME: length 55.8
  TOP w0.102: v2(49.93,28.95) U4.N13 ; U5.G8 v2(29.95,31.28)
  L5_SIG w0.114: v2(49.93,28.95) 49.93,25.9 50.36,25.47 50.36,24.77 49.86,24.27 46.13,24.27 45.61,24.8 45.61,25 45.91,25.31 45.91,25.51 45.77,25.66 45.56,25.66 45.26,25.35 45.05,25.35 44.91,25.5 44.91,25.7 45.21,26.01 45.21,26.21 45.07,26.36 44.86,26.36 44.56,26.05 44.35,26.05 44.21,26.2 44.21,26.4 44.91,27.11 44.91,27.31 44.77,27.46 44.56,27.46 43.86,26.75 43.65,26.75 43.41,27 43.41,29.13 41.8,30.73 41.6,30.73 41.18,30.32 40.98,30.32 40.83,30.46 40.83,30.67 41.25,31.08 41.25,31.29 41.1,31.43 40.9,31.43 40.48,31.02 40.28,31.02 39.78,31.51 39.78,31.79 39.92,31.93 40.84,31.93 40.99,32.08 40.99,32.28 40.84,32.43 39.92,32.43 39.78,32.57 39.78,32.78 39.92,32.93 40.34,32.93 40.49,33.07 40.49,33.28 40.34,33.42 39.43,33.42 39.28,33.28 39.28,32.35 39.14,32.2 38.93,32.2 38.79,32.35 38.79,33.43 38.64,33.57 38.44,33.57 38.29,33.43 38.29,32.35 38.15,32.2 37.94,32.2 37.8,32.35 37.8,33.43 37.65,33.57 37.45,33.57 37.3,33.43 37.3,32.35 37.16,32.2 36.95,32.2 36.81,32.35 36.81,33.23 36.66,33.37 35.64,33.37 35.45,33.18 35.45,32.94 35.59,32.79 36.2,32.79 36.35,32.65 36.35,32.44 36.2,32.3 35.59,32.3 35.45,32.15 35.45,31.88 35.25,31.68 35.06,31.68 34.92,31.82 34.92,32.23 34.77,32.38 34.57,32.38 34.42,32.23 34.42,31.82 34.28,31.68 34.07,31.68 33.93,31.82 33.93,32.23 33.78,32.38 33.58,32.38 33.43,32.23 33.43,31.82 33.29,31.68 33.08,31.68 32.94,31.82 32.94,32.23 32.79,32.38 32.59,32.38 32.44,32.23 32.44,31.82 32.3,31.68 32.09,31.68 31.95,31.82 31.95,32.23 31.8,32.38 31.6,32.38 31.45,32.23 31.45,31.82 31.31,31.68 30.35,31.68 v2(29.95,31.28)
IO_L08_34_CTRL_OUT0: length 30.4
  TOP w0.102: U4.L15 51.93,27.04 49.97,25.08 48.09,25.08 v2(47.13,26.05) ; U5.D4 v2(32.34,34.48)
  L5_SIG w0.114: v2(32.34,34.48) 32.75,34.88 32.75,36.28 32.95,36.48 35.07,36.48 35.91,35.63 40.99,35.63 42.52,34.11 42.52,32.45 45.95,29.02 45.95,28.52 46.23,28.25 46.83,28.25 47.13,27.94 v2(47.13,26.05)
IO_L08_34_CTRL_OUT1: length 31.1
  TOP w0.102: v2(48.73,26.05) 49.1,25.67 49.76,25.67 51.13,27.04 U4.M15 ; U5.E4 v2(31.54,34.48)
  L5_SIG w0.114: v2(48.73,26.05) 48.73,28.55 48.23,29.05 46.83,29.05 45.73,30.15 45.33,30.15 43.62,31.85 43.62,32.75 42.9,33.47 42.9,34.24 41.12,36.01 36.42,36.01 35.15,37.28 32.15,37.28 31.95,37.08 31.95,34.88 v2(31.54,34.48)
IO_L09_34_TX_FRAME: length 28.8
  TOP w0.102: v2(52.33,28.15) U4.L14 ; v2(29.94,30.48) U5.G9
  L6_SIG w0.114: v2(29.94,30.48) 30.34,30.08 30.34,26.78 30.94,26.18 31.38,26.18 32.34,25.22 49.4,25.22 v2(52.33,28.15)
IO_L10_34_EN_AGC: length 35.1
  TOP w0.102: U5.G5 v2(29.14,33.68) ; U4.L13 51.46,28.88 51.46,26.97 49.86,25.37 48.6,25.37 v2(47.93,26.05)
  L5_SIG w0.114: v2(29.14,33.68) 29.55,33.28 29.55,32.68 29.75,32.48 30.55,32.48 32.15,34.08 33.45,34.08 33.65,34.28 33.65,34.89 34.01,35.25 40.87,35.25 42.14,33.98 42.14,32.33 45.13,29.35 45.13,28.35 46.63,26.84 46.63,25.84 46.9,25.57 47.45,25.57 v2(47.93,26.05)
IO_L11_34_ENABLE: length 31.3
  TOP w0.102: U4.K12 v2(52.33,29.75) ; U5.G6 v2(29.14,32.88)
  L6_SIG w0.114: v2(29.14,32.88) 29.54,33.28 29.54,35.28 29.94,35.68 43.4,35.68 45.53,33.55 46.63,33.55 47.23,32.95 47.73,32.95 47.83,33.05 47.83,33.55 48.12,33.85 48.83,33.85 49.33,33.35 50.13,33.35 51.13,32.35 51.13,30.35 51.33,30.15 51.93,30.15 v2(52.33,29.75)
IO_L11_34_TXNRX: length 33.2
  TOP w0.102: U5.H4 v2(28.35,34.48) ; U4.K11 v2(52.33,30.55)
  L6_SIG w0.114: v2(28.35,34.48) 27.94,34.88 27.94,37.08 28.78,37.92 42.16,37.92 45.93,34.15 50.13,34.15 50.33,33.95 50.33,33.55 50.53,33.35 51.73,33.35 51.93,33.15 51.93,30.95 v2(52.33,30.55)
IO_L12_MRCC_34_DATA_CLK: length 55.5
  TOP w0.102: U4.L12 v2(51.53,29.75) ; U5.G11 v2(29.95,28.88)
  L5_SIG w0.114: v2(51.53,29.75) 51.53,29.05 50.77,28.29 50.77,24.69 50.03,23.95 45.95,23.95 44.55,25.35 44.34,25.35 43.91,24.92 43.71,24.92 43.56,25.06 43.56,25.27 43.99,25.7 43.99,25.9 43.85,26.05 43.64,26.05 43.21,25.62 43.01,25.62 42.86,25.76 42.86,25.97 43.29,26.4 43.29,26.6 43.15,26.75 42.94,26.75 42.51,26.32 42.31,26.32 42.16,26.47 42.16,26.67 42.97,27.48 42.97,27.69 42.83,27.83 42.62,27.83 41.81,27.02 41.61,27.02 41.46,27.17 41.46,27.37 42.4,28.31 42.4,28.51 42.25,28.66 42.05,28.66 40.98,27.59 40.78,27.59 40.63,27.74 40.63,27.94 42.08,29.39 42.08,29.6 41.89,29.78 41.68,29.78 40.32,28.42 40.11,28.42 39.97,28.56 39.97,28.77 40.74,29.54 40.74,29.92 40.5,30.16 40.29,30.16 39.93,29.79 39.72,29.79 39.58,29.94 39.58,30.14 39.94,30.51 39.94,30.72 39.8,30.86 39.59,30.86 38.97,30.24 38.77,30.24 38.62,30.39 38.62,30.59 39.24,31.21 39.24,31.54 38.96,31.82 38.45,31.82 38.31,31.68 38.31,31.02 38.16,30.88 37.92,30.88 37.78,31.02 37.78,31.68 37.63,31.82 37.43,31.82 37.28,31.68 37.28,31.02 37.14,30.88 36.93,30.88 36.79,31.02 36.79,31.68 36.64,31.82 36.43,31.82 36.29,31.68 36.29,30.9 36.14,30.75 35.94,30.75 35.79,30.9 35.79,31.17 35.65,31.32 35.44,31.32 35.3,31.17 35.3,31.02 35.15,30.88 30.55,30.88 30.35,30.68 30.35,29.28 v2(29.95,28.88)
IO_L13_34_CTRL_OUT2: length 29.4
  TOP w0.102: U5.E5 v2(30.74,33.68) ; U4.N11 v2(49.93,30.55)
  L5_SIG w0.114: v2(30.74,33.68) 30.74,34.68 30.25,35.18 30.25,36.28 30.44,36.48 30.94,36.48 31.21,36.75 31.21,37.28 31.98,38.05 35.41,38.05 36.71,36.75 41.41,36.75 43.53,34.62 43.53,33.94 44.22,33.25 44.52,33.25 44.93,32.85 44.93,32.25 46.13,31.05 46.13,30.75 47.13,29.74 47.83,29.74 48.63,30.55 v2(49.93,30.55)
IO_L13_34_CTRL_OUT3: length 30.3
  TOP w0.102: U5.E6 v2(31.54,32.88) ; U4.N12 v2(49.93,29.75)
  L5_SIG w0.114: v2(49.93,29.75) 49.13,28.95 49.13,25.74 48.58,25.19 46.78,25.19 46.23,25.74 46.23,26.7 44.83,28.1 44.83,29.15 42.32,31.65 41.82,31.65 41.37,32.1 41.37,33.1 39.6,34.87 34.39,34.87 34.05,34.53 34.05,33.78 33.55,33.28 31.94,33.28 v2(31.54,32.88)
IO_L15_34_TX_D0: length 23.4
  TOP w0.102: U5.E12 31.22,27.6 31.22,27.58 v2(31.53,27.27) ; U4.P15 49.53,27.45 49.15,27.07 45.51,27.07 v2(45.31,26.87)
  L6_SIG w0.114: v2(45.31,26.87) 45.95,26.87 46.2,26.62 46.2,26.36 45.82,25.98 43.49,25.98 43.23,26.24 42.78,26.24 42.52,25.98 42.15,25.98 41.89,26.24 41.44,26.24 41.19,25.98 40.82,25.98 40.56,26.24 40.11,26.24 39.85,25.98 39.48,25.98 39.22,26.24 38.77,26.24 38.52,25.98 38.14,25.98 37.88,26.24 37.43,26.24 37.18,25.98 36.8,25.98 36.55,26.24 36.1,26.24 35.84,25.98 32.44,25.98 31.53,26.89 v2(31.53,27.27)
IO_L15_34_TX_D1: length 23.2
  TOP w0.102: U5.D11 v2(32.35,28.08) ; U4.R13 48.72,29.34 48.43,29.34 48.23,29.14 45.92,29.14 v2(45.53,28.75)
  L6_SIG w0.114: v2(32.35,28.08) 32.67,28.08 32.74,28 32.74,27.88 32.95,27.68 34.94,27.68 35.41,28.14 37.69,28.14 38.45,27.38 39.2,27.38 39.35,27.52 39.35,28.12 39.49,28.27 39.7,28.27 39.84,28.12 39.84,27.52 39.99,27.38 40.19,27.38 40.34,27.52 40.34,28.12 40.48,28.27 40.69,28.27 40.83,28.12 40.83,27.52 40.98,27.38 41.18,27.38 41.33,27.52 41.33,28.12 41.47,28.27 41.68,28.27 41.83,28.12 41.83,27.52 41.97,27.38 44.04,27.38 44.43,27.76 44.43,28.35 44.83,28.75 v2(45.53,28.75)
IO_L16_34_TX_D2: length 22.7
  TOP w0.102: v2(46.43,27.75) U4.R15 ; v2(31.54,28.07) 31.53,28.08 31.53,28.09 U5.E11
  L6_SIG w0.114: v2(46.43,27.75) 47.09,27.75 47.27,27.57 47.27,27.39 47.07,27.19 46.18,27.19 45.77,27.61 45.41,27.61 44.42,26.62 36.59,26.62 36.39,26.82 36.39,27.13 36.24,27.28 36.04,27.28 35.89,27.13 35.89,26.59 35.66,26.36 32.56,26.36 31.94,26.98 31.94,27.48 31.74,27.68 31.64,27.68 31.54,27.78 v2(31.54,28.07)
IO_L16_34_TX_D3: length 23.6
  TOP w0.102: U5.D10 v2(32.34,28.88) ; v2(42.82,28.75) 43.82,29.75 47.73,29.75 48.53,30.54 49.12,30.54 U4.P11
  L6_SIG w0.114: v2(32.34,28.88) 32.74,29.28 35.65,29.28 35.95,28.98 36.95,28.98 37.55,29.58 37.79,29.58 37.94,29.43 37.94,29.07 38.08,28.92 38.29,28.92 38.43,29.07 38.43,29.43 38.58,29.58 38.78,29.58 38.93,29.43 38.93,29.19 39.07,29.05 39.28,29.05 39.42,29.19 39.42,29.43 39.57,29.58 39.77,29.58 39.92,29.43 39.92,29.19 40.06,29.05 40.27,29.05 40.41,29.19 40.41,29.43 40.56,29.58 40.76,29.58 40.91,29.43 40.91,29.19 41.05,29.05 41.26,29.05 41.49,29.28 43.28,29.28 43.41,29.16 43.41,28.9 43.25,28.75 v2(42.82,28.75)
IO_L17_34_TX_D4: length 23.2
  TOP w0.102: v2(47.53,30.15) 48.33,30.95 U4.R11 ; U5.E10 v2(31.54,28.88)
  L6_SIG w0.114: v2(47.53,30.15) 47.96,29.72 47.96,29.28 46.96,28.28 45.07,28.28 44.85,28.06 44.85,27.56 44.3,27 38.23,27 37.59,27.63 35.7,27.63 35.41,27.34 35.41,27.04 35.15,26.78 32.95,26.78 32.74,26.98 32.74,27.48 32.55,27.68 32.15,27.68 31.94,27.88 31.94,28.28 31.74,28.48 31.62,28.48 31.54,28.55 v2(31.54,28.88)
IO_L17_34_TX_D5: length 22.7
  TOP w0.102: v2(43.83,28.75) 44.52,29.45 48,29.45 48.13,29.57 48.15,29.57 U4.R12 ; U5.D9 v2(32.34,29.68)
  L6_SIG w0.114: v2(32.34,29.68) 32.75,30.08 35.35,30.08 36.05,29.38 36.75,29.38 37.35,29.98 41.06,29.98 41.37,29.66 43.6,29.66 43.93,29.99 43.93,30.3 44.08,30.45 44.93,30.45 45.31,30.06 45.31,29.74 44.32,28.75 v2(43.83,28.75)
IO_L18_34_TX_D6: length 22.9
  TOP w0.102: U4.P14 49.13,28.14 49.13,27.55 48.95,27.37 44.4,27.37 v2(43.83,27.95) ; U5.E9 v2(31.54,29.68)
  L6_SIG w0.114: v2(43.83,27.95) 43.21,27.95 43.03,27.76 42.52,27.76 42.26,28.01 42.26,28.67 42.05,28.88 41.73,28.88 41.5,28.65 39.09,28.65 38.87,28.43 38.87,28 38.75,27.88 38.48,27.88 38.35,28 38.35,28.38 38.21,28.52 35.2,28.52 34.85,28.88 34.6,28.88 34.46,28.73 34.46,28.62 34.31,28.48 32.19,28.48 31.94,28.72 31.94,29.28 v2(31.54,29.68)
IO_L18_34_TX_D7: length 22.7
  TOP w0.102: U5.D8 v2(32.34,30.48) ; U4.P13 49.12,28.94 48.42,28.94 48.23,28.75 46.63,28.75 46.63,28.75 v2(46.42,28.75)
  L6_SIG w0.114: v2(32.34,30.48) 32.75,30.88 35.15,30.88 35.65,30.38 41.31,30.38 41.46,30.52 41.46,30.74 41.6,30.88 41.94,30.88 42.08,30.74 42.08,30.52 42.23,30.38 42.43,30.38 42.58,30.52 42.58,30.74 42.72,30.88 45.05,30.88 45.76,30.17 46.33,30.17 46.6,30.45 46.93,30.45 47.13,30.25 47.13,28.95 46.92,28.75 v2(46.42,28.75)
IO_L19_34_TX_D8: length 22.6
  TOP w0.102: U4.N9 49.93,32.15 47.92,32.15 v2(47.52,31.75) ; U5.E8 v2(31.54,30.48)
  L6_SIG w0.114: v2(47.52,31.75) 44.93,31.75 44.86,31.68 38.85,31.68 38.71,31.82 37.69,31.82 37.45,31.58 37.45,31.32 37.31,31.18 37.1,31.18 36.96,31.32 36.96,31.63 36.81,31.78 36.6,31.78 36.46,31.63 36.46,31.32 36.31,31.18 36.11,31.18 35.96,31.32 35.96,31.76 35.75,31.98 32.45,31.98 31.94,31.47 31.94,30.88 v2(31.54,30.48)
IO_L19_34_TX_D9: length 22.9
  TOP w0.102: U5.D7 v2(32.34,31.28) ; v2(49.93,32.95) 50.73,32.95 U4.M9
  L6_SIG w0.114: v2(32.34,31.28) 32.35,31.28 32.75,31.68 34.95,31.68 35.85,30.78 37.77,30.78 37.92,30.92 37.92,31.13 38.06,31.28 38.27,31.28 38.41,31.13 38.41,30.92 38.56,30.78 38.76,30.78 38.91,30.92 38.91,31.13 39.05,31.28 39.26,31.28 39.4,31.13 39.4,30.92 39.55,30.78 39.75,30.78 39.9,30.92 39.9,31.13 40.04,31.28 40.25,31.28 40.39,31.13 40.39,30.92 40.54,30.78 40.85,30.78 41.35,31.28 45.36,31.28 45.43,31.36 48.34,31.36 v2(49.93,32.95)
